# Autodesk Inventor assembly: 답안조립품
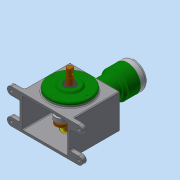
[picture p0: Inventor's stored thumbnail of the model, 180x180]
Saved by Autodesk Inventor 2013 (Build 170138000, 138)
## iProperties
Created: 2016-11
Part Number: 답안조립품
Document SubType Name: Assembly
Designer: dgall
Author: dgall
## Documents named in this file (16)
- C:\Users\dgall\Desktop\361107V1008\답안조립품.iam
- C:\Users\dgall\Desktop\361107V1008\본체.ipt
- C:\Users\dgall\Desktop\361107V1008\가변스프링.ipt
- C:\Users\dgall\Desktop\361107V1008\메인크랭크축.ipt
- C:\Users\dgall\Desktop\361107V1008\베어링 20 x 47 x 14.ipt
- C:\Users\dgall\Desktop\361107V1008\베어링 NA 4902.ipt
- C:\Users\dgall\Desktop\361107V1008\크랭크보조축.ipt
- C:\Users\dgall\Desktop\361107V1008\실린더.ipt
- C:\Users\dgall\Desktop\361107V1008\커넥팅로드.ipt
- C:\Users\dgall\Desktop\361107V1008\피스톤.ipt
- C:\Users\dgall\Desktop\361107V1008\피스톤핀.ipt
- C:\Users\dgall\Desktop\361107V1008\볼트 M4 x 8.ipt
- C:\Users\dgall\Desktop\361107V1008\앞커버.ipt
- C:\Users\dgall\Desktop\361107V1008\볼트 M5 x 20.ipt
- C:\Users\dgall\Desktop\361107V1008\실린더헤드.ipt
- C:\Users\dgall\Desktop\361107V1008\오일 실 20 35 8.ipt
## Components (15 placed, 5 different names)
1. 가변스프링:1
2. 피스톤:1
3. 피스톤핀:1
4. ISO 4762 M4 x 8:5
5. ISO 4762 M4 x 8:6
6. ISO 4762 M4 x 8:7
7. ISO 4762 M4 x 8:8
8. ISO 4762 M4 x 8:1
9. ISO 4762 M4 x 8:2
10. ISO 4762 M4 x 8:3
11. ISO 4762 M4 x 8:4
12. ISO 4762 M5 x 20:2
13. ISO 4762 M5 x 20:3
14. ISO 4762 M5 x 20:4
15. ISO 4762 M5 x 20:5
